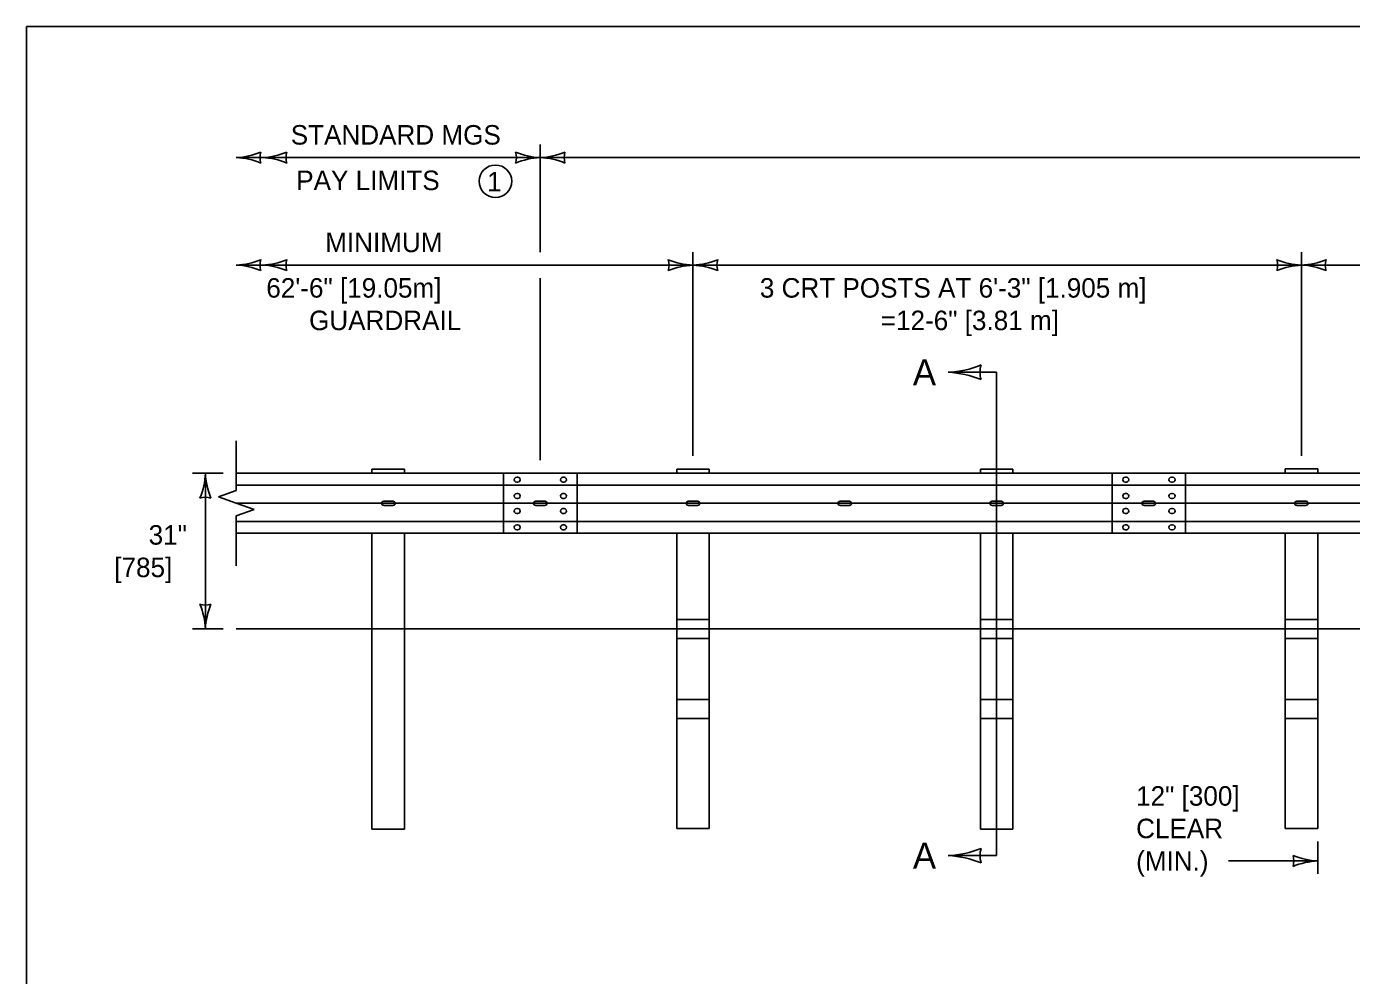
# Model space of a CAD drawing. Extents: x 49991.4 to 50021, y 49987.6 to 50011.4.
# Drawn here: x 49999.384 to 50003.461, y 49996.08 to 49998.999 of the extents above; entities that cross this region are included whole.
import ezdxf

# ---------------------------------------------------------------- set-up
doc = ezdxf.new("R2010")
doc.units = 0
for name, color, linetype in [('Level 1', 7, 'Continuous'), ('Level 2', 7, 'Continuous'), ('Level 3', 7, 'Continuous'), ('Level 4', 7, 'Continuous'), ('Level 5', 7, 'Continuous'), ('Level 6', 7, 'Continuous')]:
    doc.layers.add(name, color=color, linetype=linetype)

msp = doc.modelspace()

# ---------------------------------------------------------------- linework, layer by layer
at = {"layer": 'Level 1'}
for p, q in [((50000.0289, 49997.6246), (50011.2949, 49997.6246)), ((50000.4461, 49997.6378), (50000.4461, 49997.6246)), ((50000.4461, 49997.6378), (50000.5461, 49997.6378)), ((50000.5461, 49997.6246), (50000.5461, 49997.6378)), ((50001.3842, 49997.6246), (50001.3842, 49997.6378)), ((50001.3842, 49997.6378), (50001.4841, 49997.6378)), ((50001.4841, 49997.6246), (50001.4841, 49997.6378)), ((50002.3186, 49997.6378), (50002.3186, 49997.6246)), ((50002.3186, 49997.6378), (50002.4186, 49997.6378)), ((50002.4186, 49997.6246), (50002.4186, 49997.6378)), ((50003.2567, 49997.6246), (50003.2567, 49997.6379)), ((50003.2567, 49997.6379), (50003.3566, 49997.6379)), ((50003.3566, 49997.6246), (50003.3566, 49997.6379)), ((50000.0289, 49997.5886), (50011.2949, 49997.5886)), ((50000.8512, 49997.4394), (50000.8512, 49997.6239)), ((50000.8954, 49997.6123), (50000.8918, 49997.6123)), ((50000.8954, 49997.5973), (50000.8918, 49997.5973)), ((50001.0376, 49997.6123), (50001.034, 49997.6123)), ((50001.0376, 49997.5973), (50001.034, 49997.5973)), ((50002.7236, 49997.4394), (50002.7236, 49997.6239)), ((50002.7678, 49997.6123), (50002.7642, 49997.6123)), ((50002.7678, 49997.5973), (50002.7642, 49997.5973)), ((50002.9101, 49997.6123), (50002.9065, 49997.6123)), ((50002.9101, 49997.5973), (50002.9065, 49997.5973)), ((50000.8954, 49997.5624), (50000.8918, 49997.5624)), ((50000.8954, 49997.5474), (50000.8918, 49997.5474)), ((50001.0376, 49997.5624), (50001.034, 49997.5624)), ((50001.0376, 49997.5474), (50001.034, 49997.5474)), ((50002.7678, 49997.5624), (50002.7642, 49997.5624)), ((50002.7678, 49997.5474), (50002.7642, 49997.5474)), ((50002.9101, 49997.5624), (50002.9065, 49997.5624)), ((50002.9101, 49997.5474), (50002.9065, 49997.5474)), ((50000.4826, 49997.5386), (50000.5117, 49997.5386)), ((50000.4826, 49997.5261), (50000.5117, 49997.5261)), ((50000.8954, 49997.516), (50000.8918, 49997.516)), ((50000.9498, 49997.5386), (50000.979, 49997.5386)), ((50000.9498, 49997.5261), (50000.979, 49997.5261)), ((50001.0376, 49997.516), (50001.034, 49997.516)), ((50001.4196, 49997.5386), (50001.4487, 49997.5386)), ((50001.4196, 49997.5261), (50001.4487, 49997.5261)), ((50001.8868, 49997.5386), (50001.916, 49997.5386)), ((50001.8868, 49997.5261), (50001.916, 49997.5261)), ((50002.354, 49997.5386), (50002.3832, 49997.5386)), ((50002.354, 49997.5261), (50002.3832, 49997.5261)), ((50002.7678, 49997.516), (50002.7642, 49997.516)), ((50002.8223, 49997.5386), (50002.8514, 49997.5386)), ((50002.8223, 49997.5261), (50002.8514, 49997.5261)), ((50002.9101, 49997.516), (50002.9065, 49997.516)), ((50003.292, 49997.5386), (50003.3212, 49997.5386)), ((50003.292, 49997.5261), (50003.3212, 49997.5261)), ((50000.0289, 49997.4761), (50011.2949, 49997.4761)), ((50000.8954, 49997.5009), (50000.8918, 49997.5009)), ((50000.8954, 49997.4661), (50000.8918, 49997.4661)), ((50001.0376, 49997.5009), (50001.034, 49997.5009)), ((50001.0376, 49997.4661), (50001.034, 49997.4661)), ((50002.7678, 49997.5009), (50002.7642, 49997.5009)), ((50002.7678, 49997.4661), (50002.7642, 49997.4661)), ((50002.9101, 49997.5009), (50002.9065, 49997.5009)), ((50002.9101, 49997.4661), (50002.9065, 49997.4661)), ((50000.0289, 49997.4401), (50011.2949, 49997.4401)), ((50000.4461, 49997.1457), (50000.4461, 49997.4401)), ((50000.5461, 49997.1457), (50000.5461, 49997.4401)), ((50000.8954, 49997.451), (50000.8918, 49997.451)), ((50001.0376, 49997.451), (50001.034, 49997.451)), ((50001.3841, 49997.1457), (50001.3841, 49997.4401)), ((50001.4841, 49997.1457), (50001.4841, 49997.4401)), ((50002.3186, 49997.1457), (50002.3186, 49997.4401)), ((50002.4185, 49997.1457), (50002.4185, 49997.4401)), ((50002.7678, 49997.451), (50002.7642, 49997.451)), ((50002.9101, 49997.451), (50002.9065, 49997.451)), ((50003.2566, 49997.1457), (50003.2566, 49997.4401)), ((50003.3566, 49997.1457), (50003.3566, 49997.4401)), ((50011.2949, 49997.1457), (50000.0289, 49997.1457))]:
    msp.add_line(p, q, dxfattribs=at)
msp.add_lwpolyline([(49999.3835, 49998.9992), (50016.7501, 49998.9992), (50016.7501, 49987.7988), (49999.3835, 49987.7988)], close=True, dxfattribs=at)
for centre, start, end in [((50000.4826, 49997.5324), 90, 180), ((50000.4826, 49997.5324), 180, 270), ((50000.5117, 49997.5324), 360, 90), ((50000.5117, 49997.5324), 270, 0), ((50000.9498, 49997.5324), 90, 180), ((50000.9498, 49997.5324), 180, 270), ((50000.979, 49997.5324), 360, 90), ((50000.979, 49997.5324), 270, 0), ((50001.4196, 49997.5324), 90, 180), ((50001.4196, 49997.5324), 180, 270), ((50001.4487, 49997.5324), 360, 90), ((50001.4487, 49997.5324), 270, 0), ((50001.8868, 49997.5324), 90, 180), ((50001.8868, 49997.5324), 180, 270), ((50001.916, 49997.5324), 360, 90), ((50001.916, 49997.5324), 270, 0), ((50002.354, 49997.5324), 90, 180), ((50002.354, 49997.5324), 180, 270), ((50002.3832, 49997.5324), 360, 90), ((50002.3832, 49997.5324), 270, 0), ((50002.8223, 49997.5324), 90, 180), ((50002.8223, 49997.5324), 180, 270), ((50002.8514, 49997.5324), 360, 90), ((50002.8514, 49997.5324), 270, 0), ((50003.292, 49997.5324), 90, 180), ((50003.292, 49997.5324), 180, 270), ((50003.3212, 49997.5324), 360, 90), ((50003.3212, 49997.5324), 270, 0)]:
    msp.add_arc(centre, 0.00625, start, end, dxfattribs=at)
for centre, start_param, end_param in [((50000.8918, 49997.6048), 1.570796, 4.712389), ((50000.8954, 49997.6048), 4.712389, 7.853982), ((50001.034, 49997.6048), 1.570796, 4.712389), ((50001.0376, 49997.6048), 4.712389, 7.853982), ((50002.7642, 49997.6048), 1.570796, 4.712389), ((50002.7678, 49997.6048), 4.712389, 7.853982), ((50002.9065, 49997.6048), 1.570796, 4.712389), ((50002.9101, 49997.6048), 4.712389, 7.853982), ((50000.8918, 49997.5549), 1.570796, 4.712389), ((50000.8954, 49997.5549), 4.712389, 7.853982), ((50001.034, 49997.5549), 1.570796, 4.712389), ((50001.0376, 49997.5549), 4.712389, 7.853982), ((50002.7642, 49997.5549), 1.570796, 4.712389), ((50002.7678, 49997.5549), 4.712389, 7.853982), ((50002.9065, 49997.5549), 1.570796, 4.712389), ((50002.9101, 49997.5549), 4.712389, 7.853982), ((50000.8918, 49997.5084), 1.570796, 4.712389), ((50000.8954, 49997.5084), 4.712389, 7.853982), ((50001.034, 49997.5084), 1.570796, 4.712389), ((50001.0376, 49997.5084), 4.712389, 7.853982), ((50002.7642, 49997.5084), 1.570796, 4.712389), ((50002.7678, 49997.5084), 4.712389, 7.853982), ((50002.9065, 49997.5084), 1.570796, 4.712389), ((50002.9101, 49997.5084), 4.712389, 7.853982), ((50000.8918, 49997.4585), 1.570796, 4.712389), ((50000.8954, 49997.4585), 4.712389, 7.853982), ((50001.034, 49997.4585), 1.570796, 4.712389), ((50001.0376, 49997.4585), 4.712389, 7.853982), ((50002.7642, 49997.4585), 1.570796, 4.712389), ((50002.7678, 49997.4585), 4.712389, 7.853982), ((50002.9065, 49997.4585), 1.570796, 4.712389), ((50002.9101, 49997.4585), 4.712389, 7.853982)]:
    msp.add_ellipse(centre, major_axis=(0.00756, 0), ratio=0.998676, start_param=start_param, end_param=end_param, dxfattribs=at)
at = {"layer": 'Level 2'}
msp.add_circle((50000.8264, 49998.5231), 0.05, dxfattribs=at)
at = {"layer": 'Level 3'}
for p, q in [((50000.9644, 49998.3051), (50000.9644, 49998.6359)), ((50011.2949, 49998.5959), (50000.0289, 49998.5959)), ((50001.4342, 49997.6779), (50001.4342, 49998.3051)), ((50003.3066, 49997.6779), (50003.3066, 49998.3051)), ((50001.4342, 49998.2651), (50000.0289, 49998.2651)), ((50003.3066, 49998.2651), (50001.4342, 49998.2651)), ((50007.0444, 49998.2651), (50003.3066, 49998.2651)), ((50000.9644, 49997.6646), (50000.9644, 49998.2251)), ((49999.894, 49997.6246), (49999.9889, 49997.6246)), ((49999.934, 49997.1457), (49999.934, 49997.6246)), ((49999.894, 49997.1457), (49999.9889, 49997.1457)), ((50003.3566, 49996.4915), (50003.3566, 49996.3921)), ((50003.3566, 49996.4321), (50003.0816, 49996.4321))]:
    msp.add_line(p, q, dxfattribs=at)
for centre, radius, start, end in [((50000.0174, 49998.8286), 0.233, 272.8273, 292.0772), ((50000.1571, 49998.5959), 0.0548, 162.1388, 197.8612), ((50000.0973, 49998.8286), 0.233, 272.8273, 292.0772), ((50000.237, 49998.5959), 0.0548, 162.1388, 197.8612), ((50000.9735, 49998.818), 0.2223, 247.456, 267.6395), ((50000.8362, 49998.5959), 0.0548, 342.1388, 17.8612), ((50000.9529, 49998.8286), 0.233, 272.8273, 292.0772), ((50001.0926, 49998.5959), 0.0548, 162.1388, 197.8612), ((50000.0197, 49998.3738), 0.2223, 67.456, 87.6395), ((50000.0997, 49998.3738), 0.2223, 67.456, 87.6395), ((50000.9759, 49998.3632), 0.233, 92.8273, 112.0772), ((50000.9552, 49998.3738), 0.2223, 67.456, 87.6395), ((50000.0174, 49998.4978), 0.233, 272.8273, 292.0772), ((50000.1571, 49998.2651), 0.0548, 162.1388, 197.8612), ((50000.0973, 49998.4978), 0.233, 272.8273, 292.0772), ((50000.237, 49998.2651), 0.0548, 162.1388, 197.8612), ((50001.4433, 49998.4872), 0.2223, 247.456, 267.6395), ((50001.3059, 49998.2651), 0.0548, 342.1388, 17.8612), ((50001.425, 49998.4872), 0.2223, 272.3605, 292.544), ((50001.5624, 49998.2651), 0.0548, 162.1388, 197.8612), ((50003.3158, 49998.4872), 0.2223, 247.456, 267.6395), ((50003.1784, 49998.2651), 0.0548, 342.1388, 17.8612), ((50003.2951, 49998.4978), 0.233, 272.8273, 292.0772), ((50003.4348, 49998.2651), 0.0548, 162.1388, 197.8612), ((50000.0197, 49998.043), 0.2223, 67.456, 87.6395), ((50000.0997, 49998.043), 0.2223, 67.456, 87.6395), ((50001.4457, 49998.0324), 0.233, 92.8273, 112.0772), ((50001.4227, 49998.0324), 0.233, 67.9228, 87.1727), ((50003.3181, 49998.0324), 0.233, 92.8273, 112.0772), ((50003.2975, 49998.043), 0.2223, 67.456, 87.6395), ((50002.2073, 49998.2316), 0.2964, 272.3605, 292.544), ((50002.3904, 49997.9355), 0.073, 162.1388, 197.8612), ((50002.2041, 49997.6252), 0.3107, 67.9228, 87.1727), ((49999.7119, 49997.6338), 0.2223, 337.456, 357.6395), ((50000.1667, 49997.6361), 0.233, 182.8273, 202.0772), ((49999.934, 49997.4964), 0.0548, 72.1388, 107.8612), ((49999.934, 49997.2739), 0.0548, 252.1388, 287.8612), ((49999.7013, 49997.1342), 0.233, 2.8273, 22.0772), ((50000.1561, 49997.1365), 0.2223, 157.456, 177.6395), ((50002.2042, 49996.7586), 0.3107, 272.8273, 292.0772), ((50002.2074, 49996.1522), 0.2964, 67.456, 87.6395), ((50002.3905, 49996.4484), 0.073, 162.1388, 197.8612), ((50003.3658, 49996.6542), 0.2223, 247.456, 267.6395), ((50003.2284, 49996.4321), 0.0548, 342.1388, 17.8612), ((50003.3681, 49996.1994), 0.233, 92.8273, 112.0772)]:
    msp.add_arc(centre, radius, start, end, dxfattribs=at)
at = {"layer": 'Level 4'}
for p, q in [((50001.0776, 49997.4394), (50001.0776, 49997.6239)), ((50002.9501, 49997.4394), (50002.9501, 49997.6239)), ((50000.4461, 49997.1457), (50000.4461, 49996.5303)), ((50000.5461, 49997.1457), (50000.5461, 49996.5303)), ((50001.3841, 49997.1457), (50001.3841, 49996.5316)), ((50001.3842, 49997.1747), (50001.4841, 49997.1747)), ((50001.4841, 49997.1457), (50001.4841, 49996.5316)), ((50002.3186, 49997.1747), (50002.4185, 49997.1747)), ((50002.3186, 49997.1457), (50002.3186, 49996.5303)), ((50002.4185, 49997.1457), (50002.4185, 49996.5303)), ((50003.2566, 49997.1457), (50003.2566, 49996.5315)), ((50003.2567, 49997.1748), (50003.3566, 49997.1748)), ((50003.3566, 49997.1457), (50003.3566, 49996.5315)), ((50001.3842, 49997.1164), (50001.4841, 49997.1164)), ((50002.3186, 49997.1164), (50002.4185, 49997.1164)), ((50003.2567, 49997.1165), (50003.3566, 49997.1165)), ((50001.3842, 49996.9286), (50001.4841, 49996.9286)), ((50002.3186, 49996.9286), (50002.4185, 49996.9286)), ((50003.2567, 49996.9287), (50003.3566, 49996.9287)), ((50001.3842, 49996.8703), (50001.4841, 49996.8703)), ((50002.3186, 49996.8703), (50002.4185, 49996.8703)), ((50003.2567, 49996.8704), (50003.3566, 49996.8704)), ((50000.5461, 49996.5303), (50000.4461, 49996.5303)), ((50001.4841, 49996.5316), (50001.3841, 49996.5316)), ((50002.4185, 49996.5303), (50002.3186, 49996.5303)), ((50003.3566, 49996.5315), (50003.2566, 49996.5315))]:
    msp.add_line(p, q, dxfattribs=at)
at = {"layer": 'Level 5'}
msp.add_line((50011.2949, 49997.5324), (50000.0289, 49997.5324), dxfattribs=at)
at = {"layer": 'Level 6'}
for p, q in [((50002.3685, 49997.9355), (50002.2195, 49997.9355)), ((50002.3686, 49996.4484), (50002.3685, 49997.9355)), ((50000.0289, 49997.7246), (50000.0289, 49997.5713)), ((49999.974, 49997.5519), (50000.0289, 49997.5713)), ((49999.974, 49997.5519), (50000.0289, 49997.5324)), ((50000.0289, 49997.5324), (50000.0837, 49997.513)), ((50000.0289, 49997.4935), (50000.0837, 49997.513)), ((50000.0289, 49997.4935), (50000.0289, 49997.34)), ((50002.2196, 49996.4484), (50002.3686, 49996.4484))]:
    msp.add_line(p, q, dxfattribs=at)

# ---------------------------------------------------------------- texts
at = {"layer": 'Level 2'}
for s, height, p in [('STANDARD MGS', 0.06, (50000.1966, 49998.6359)), ('PAY LIMITS', 0.06, (50000.2135, 49998.4959)), ('1', 0.06, (50000.8007, 49998.4916)), ('MINIMUM', 0.06, (50000.3026, 49998.3051)), (' 62\'-6" [19.05m]', 0.06, (50000.0991, 49998.1651)), ('3 CRT POSTS AT 6\'-3" [1.905 m]', 0.06, (50001.64, 49998.1651)), ('GUARDRAIL', 0.06, (50000.253, 49998.0651)), (' =12-6" [3.81 m] ', 0.06, (50001.9899, 49998.0651)), ('A', 0.0799, (50002.1109, 49997.8955)), ('31"', 0.06, (49999.7594, 49997.4052)), ('[785]', 0.06, (49999.6536, 49997.3052)), ('12" [300]', 0.06, (50002.7978, 49996.6021)), ('CLEAR', 0.06, (50002.7978, 49996.5021)), ('A', 0.08, (50002.1109, 49996.4084)), ('(MIN.)', 0.06, (50002.7978, 49996.4021))]:
    msp.add_text(s, height=height, dxfattribs=at).set_placement(p)

doc.saveas('drawing.dxf')
